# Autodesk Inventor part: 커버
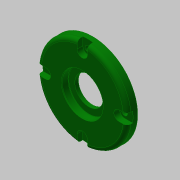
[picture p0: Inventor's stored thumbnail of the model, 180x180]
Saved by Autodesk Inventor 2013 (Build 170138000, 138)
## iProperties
Created: 2020-05
Part Number: 커버
Material: 알루미늄 6061
Document SubType Name: Modeling
Designer: mduedu
Density: 1 g/cm^3
Author: mduedu
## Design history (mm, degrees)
sketch "스케치1"
  geometry: L1 (0, 0)-(8, 0); L2 (8, 0)-(8, 35); L3 (8, 35)-(0, 35); L4 (0, 35)-(0, 0); L5 (8, 0)-(12, 0); L6 (12, 0)-(12, 23.5); L7 (12, 23.5)-(8, 23.5); L8 (8, 23.5)-(8, 0)
  constraints: 16 end point, 4 parallel, 2 horizontal, 2 perpendicular
  dimensions: "d0" = 70 diameter of L3 L1; "d2" = 47 diameter of L7 L5; "d3" = 4 distance of L6.end L7.end; "d4" = 12 distance between parallel lines of L4 L6
revolve "회전1" sketch "스케치1" stored, may be unused: angle "d5" = 90 deg
hole "구멍1" diameter "d8" = 22; stored, may be unused: countersink angle "d12" = 90 deg, drill point angle "d14" = 118 deg; dims "d6" = 10, "d7" = 10, "d9" = 6, "d10" = 32, "d11" = 5.2, "d13" = 8
hole "구멍2" diameter "d17" = 40; stored, may be unused: countersink angle "d21" = 90 deg, drill point angle "d23" = 0 deg; dims "d15" = 10, "d16" = 10, "d18" = 6, "d19" = 32, "d20" = 5.2, "d22" = 4
fillet "모깎기1" dims "d24" = 3
fillet "모깎기2" dims "d25" = 3
fillet "모깎기3" dims "d26" = 0.3
chamfer "모따기1" distance "d27" = 0.5; stored, may be unused: second distance "d28" = 2, angle "d29" = 30 deg
chamfer "모따기2" distance "d30" = 1; stored, may be unused: second distance "d31" = 2, angle "d32" = 30 deg
sketch "스케치2" dims "d33" = 57
  geometry: L1 (-4, 28.5)-(4, 28.5); L2 (4, 28.5)-(4, 38.5); L3 (4, 38.5)-(-4, 38.5); L4 (-4, 38.5)-(-4, 28.5); 4 further points
  constraints: 8 end point, 2 horizontal alignment, 2 midpoint, 2 parallel, 2 vertical alignment, 1 coincident, 1 horizontal, 1 perpendicular, 6 other
  dimensions: "d34" = 8 distance between parallel lines of L2 L4; "d35" = 10 distance of point (0, 28.5) point (0, 38.5)
extrude "돌출1" cut sketch "스케치2" distance "d36" = 4.4; taper "d37" = 0 deg
sketch "스케치3"
  geometry: A1 r 4 centre (0, 28.5) between (-4, 28.5) and (4, 28.5) reference; 2 further points
  constraints: 1 coincident
hole "구멍3" sketch "스케치3" at (0, 28.5) diameter "d38" = 4.5; stored, may be unused: countersink angle "d42" = 90 deg, drill point angle "d44" = 0 deg; dims "d39" = 6, "d40" = 32, "d41" = 5.2, "d43" = 4
node "솔리드1"
pattern_circular "원형 패턴1" dims angle "d46" = 360 deg
